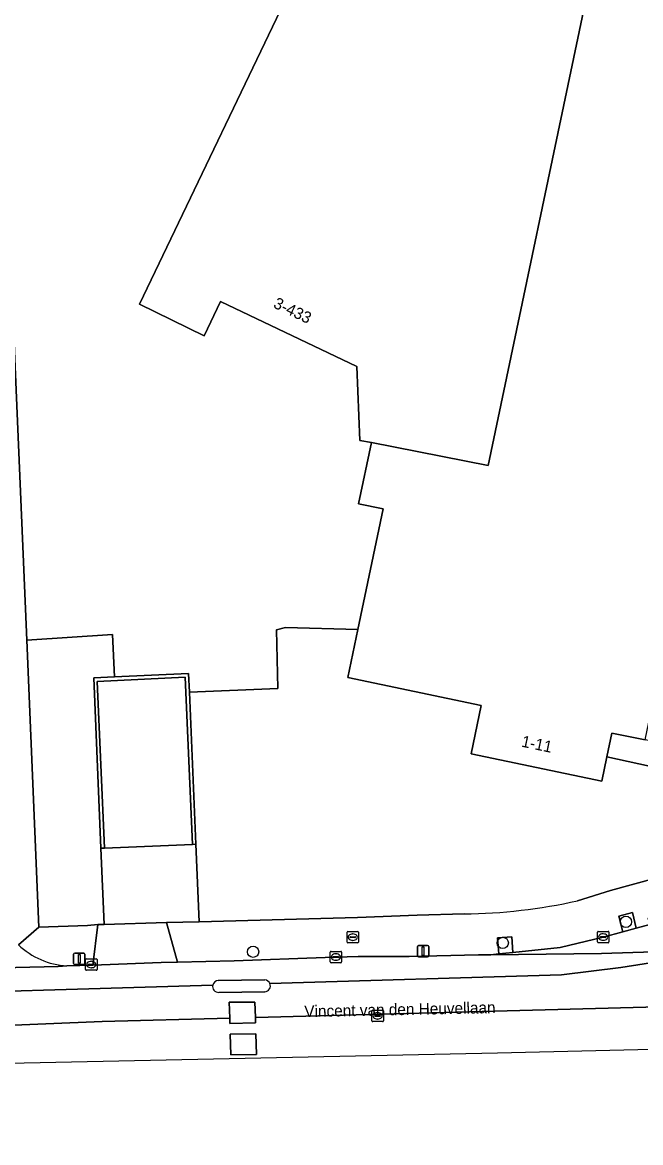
# Model space of a CAD drawing. Extents: x 161241 to 161758, y 384138 to 384885.
# Drawn here: x 161385.2 to 161439, y 384139.3 to 384236.8 of the extents above; entities that cross this region are included whole.
import ezdxf

# ---------------------------------------------------------------- set-up
doc = ezdxf.new("R2010")
doc.units = 0
for name, color, linetype in [('IMGEO_Boom', 7, 'Continuous'), ('IMGEO_Brandkraan', 7, 'Continuous'), ('IMGEO_Erf', 7, 'Continuous'), ('IMGEO_Fietspad_gesloten', 7, 'Continuous'), ('IMGEO_Groenvoorziening', 7, 'Continuous'), ('IMGEO_Kolk', 7, 'Continuous'), ('IMGEO_Lichtmast', 7, 'Continuous'), ('IMGEO_Muur', 7, 'Continuous'), ('IMGEO_Openbare_ruimte_label', 7, 'Continuous'), ('IMGEO_Pand', 7, 'Continuous'), ('IMGEO_Pand_nummerreeks', 7, 'Continuous'), ('IMGEO_Rijbaan_lokaal_gesloten', 7, 'Continuous'), ('IMGEO_Rijbaan_lokaal_open', 7, 'Continuous'), ('IMGEO_Rioolput', 7, 'Continuous'), ('IMGEO_Verkeerseiland_open', 7, 'Continuous'), ('IMGEO_Voetpad_open', 7, 'Continuous')]:
    doc.layers.add(name, color=color, linetype=linetype)

msp = doc.modelspace()

# ---------------------------------------------------------------- linework, layer by layer
at = {"layer": 'IMGEO_Boom'}
for centre in [(161437.743, 384158.555), (161427.028, 384156.723), (161405.286, 384155.947)]:
    msp.add_circle(centre, 0.489, dxfattribs=at)
at = {"layer": 'IMGEO_Brandkraan'}
for p, q in [((161413.464, 384156.795), (161413.464, 384157.647)), ((161413.539, 384157.721), (161414.391, 384157.721)), ((161413.723, 384157.215), (161413.723, 384157.227)), ((161414.161, 384157.178), (161413.763, 384157.178)), ((161413.766, 384157.264), (161414.164, 384157.264)), ((161413.952, 384157.501), (161413.977, 384157.501)), ((161414.207, 384157.227), (161414.207, 384157.215)), ((161414.465, 384157.647), (161414.465, 384156.795)), ((161414.391, 384156.721), (161413.539, 384156.721)), ((161413.975, 384156.941), (161413.95, 384156.941))]:
    msp.add_line(p, q, dxfattribs=at)
for points in [[(161413.464, 384156.795), (161413.464, 384157.647)], [(161413.539, 384157.721), (161414.391, 384157.721)], [(161414.465, 384157.647), (161414.465, 384156.795)], [(161414.391, 384156.721), (161413.539, 384156.721)]]:
    msp.add_lwpolyline(points, dxfattribs=at)
for centre, radius, start, end in [((161413.541, 384157.645), 0.0765, 91.55205, 178.44795), ((161413.541, 384157.645), 0.0765, 91.55205, 178.44795), ((161413.763, 384157.224), 0.0403, 85.87752, 175.75265), ((161413.76, 384157.214), 0.0366, 178.93798, 274.71019), ((161414.164, 384157.221), 0.043, 264.86636, 352.45326), ((161414.168, 384157.226), 0.0386, 1.73085, 96.63898), ((161414.389, 384157.645), 0.0765, 1.55205, 88.44795), ((161414.389, 384157.645), 0.0765, 1.55205, 88.44795), ((161413.541, 384156.797), 0.0765, 181.55205, 268.44795), ((161413.541, 384156.797), 0.0765, 181.55205, 268.44795), ((161414.389, 384156.797), 0.0765, 271.55205, 358.44795), ((161414.389, 384156.797), 0.0765, 271.55205, 358.44795)]:
    msp.add_arc(centre, radius, start, end, dxfattribs=at)
for centre, major_axis, ratio, start_param, end_param in [((161413.951, 384157.221), (-0.387, 0.002), 0.722429, 4.712389, 7.853982), ((161413.976, 384157.221), (-0.39, 0.002), 0.717154, 1.570796, 4.712389)]:
    msp.add_ellipse(centre, major_axis=major_axis, ratio=ratio, start_param=start_param, end_param=end_param, dxfattribs=at)
at = {"layer": 'IMGEO_Erf'}
for points in [[(161403.222, 384286.46), (161382.629, 384295.041), (161382.268, 384292.057), (161381.629, 384276.193), (161381.889, 384271.203), (161384.168, 384216.383), (161385.58, 384183.057), (161393.06, 384183.551), (161393.229, 384179.87), (161399.67, 384180.152), (161399.739, 384178.529), (161407.43, 384178.871), (161407.337, 384183.973), (161408.1, 384184.171), (161414.411, 384183.984), (161416.602, 384194.481), (161414.471, 384194.926), (161415.583, 384200.253), (161414.588, 384200.438), (161414.333, 384206.87)], [(161414.333, 384206.87), (161402.446, 384212.54), (161401.021, 384209.552), (161395.402, 384212.301), (161409.705, 384242.134), (161410.074, 384241.957), (161409.897, 384241.587), (161413.262, 384241.218), (161413.151, 384243.377), (161412.471, 384256.608), (161412.447, 384256.607), (161412.427, 384256.606), (161412.309, 384258.896), (161412.087, 384258.958), (161410.446, 384259.418), (161410.259, 384263.218), (161410.244, 384263.523), (161410.022, 384263.577), (161410.017, 384263.687), (161409.789, 384268.472), (161410.452, 384282.119), (161403.688, 384284.431), (161403.646, 384285.881)]]:
    msp.add_lwpolyline(points, dxfattribs=at)
at = {"layer": 'IMGEO_Fietspad_gesloten'}
msp.add_lwpolyline([(161458.084, 384163.277), (161449.764, 384161.023), (161448.578, 384160.702), (161444.788, 384159.674), (161439.834, 384158.33), (161438.642, 384158.007), (161437.465, 384157.687), (161435.768, 384157.227), (161432.032, 384156.309), (161427.896, 384155.889), (161426.672, 384155.766), (161425.997, 384155.697), (161435.621, 384155.795), (161447.477, 384156.186)], dxfattribs=at)
at = {"layer": 'IMGEO_Groenvoorziening'}
for points in [[(161391.41, 384179.791), (161393.229, 384179.87), (161393.06, 384183.551), (161385.58, 384183.057), (161386.637, 384158.099), (161390.867, 384158.244), (161391.76, 384158.321), (161392.317, 384158.336), (161392.037, 384164.964)], [(161438.312, 384159.38), (161437.14, 384159.04), (161437.465, 384157.687), (161438.642, 384158.007)], [(161427.801, 384157.237), (161426.576, 384157.152), (161426.672, 384155.766), (161427.896, 384155.889)]]:
    msp.add_lwpolyline(points, close=True, dxfattribs=at)
for points in [[(161424.271, 384173.178), (161425.148, 384177.381), (161413.538, 384179.804), (161414.411, 384183.984), (161408.1, 384184.171), (161407.337, 384183.973), (161407.43, 384178.871), (161399.739, 384178.529), (161400.302, 384165.307), (161400.589, 384158.56), (161414.377, 384158.936), (161419.572, 384159.122), (161423.657, 384159.253)], [(161433.522, 384160.391), (161436.394, 384161.282), (161440.318, 384162.357), (161441.305, 384166.747), (161442.601, 384171.491), (161436.086, 384172.902), (161435.648, 384170.803), (161424.271, 384173.178)]]:
    msp.add_lwpolyline(points, dxfattribs=at)
msp.add_arc((161423.309, 384205.596), 46.344, 270.43003, 282.73077, dxfattribs=at)
at = {"layer": 'IMGEO_Kolk'}
for p, q in [((161435.267, 384156.801), (161435.267, 384157.653)), ((161435.342, 384157.727), (161436.194, 384157.727)), ((161435.526, 384157.221), (161435.526, 384157.233)), ((161435.964, 384157.184), (161435.566, 384157.184)), ((161435.569, 384157.27), (161435.967, 384157.27)), ((161435.755, 384157.507), (161435.78, 384157.507)), ((161436.01, 384157.233), (161436.01, 384157.221)), ((161436.268, 384157.653), (161436.268, 384156.801)), ((161436.194, 384156.727), (161435.342, 384156.727)), ((161435.778, 384156.947), (161435.753, 384156.947)), ((161390.702, 384154.413), (161390.702, 384155.265)), ((161390.777, 384155.339), (161391.629, 384155.339)), ((161391.19, 384155.119), (161391.215, 384155.119)), ((161391.703, 384155.265), (161391.703, 384154.413)), ((161411.997, 384155.062), (161411.997, 384155.914)), ((161412.072, 384155.988), (161412.924, 384155.988)), ((161412.256, 384155.482), (161412.256, 384155.494)), ((161412.694, 384155.445), (161412.296, 384155.445)), ((161412.299, 384155.531), (161412.697, 384155.531)), ((161412.508, 384155.208), (161412.483, 384155.208)), ((161412.485, 384155.768), (161412.51, 384155.768)), ((161412.74, 384155.494), (161412.74, 384155.482)), ((161412.998, 384155.914), (161412.998, 384155.062)), ((161391.629, 384154.339), (161390.777, 384154.339)), ((161390.961, 384154.833), (161390.961, 384154.845)), ((161391.399, 384154.796), (161391.001, 384154.796)), ((161391.004, 384154.882), (161391.402, 384154.882)), ((161391.213, 384154.559), (161391.188, 384154.559)), ((161391.445, 384154.845), (161391.445, 384154.833)), ((161412.924, 384154.988), (161412.072, 384154.988))]:
    msp.add_line(p, q, dxfattribs=at)
for points in [[(161435.267, 384156.801), (161435.267, 384157.653)], [(161435.342, 384157.727), (161436.194, 384157.727)], [(161436.268, 384157.653), (161436.268, 384156.801)], [(161436.194, 384156.727), (161435.342, 384156.727)], [(161390.702, 384154.413), (161390.702, 384155.265)], [(161390.777, 384155.339), (161391.629, 384155.339)], [(161391.703, 384155.265), (161391.703, 384154.413)], [(161411.997, 384155.062), (161411.997, 384155.914)], [(161412.072, 384155.988), (161412.924, 384155.988)], [(161412.998, 384155.914), (161412.998, 384155.062)], [(161391.629, 384154.339), (161390.777, 384154.339)], [(161412.924, 384154.988), (161412.072, 384154.988)]]:
    msp.add_lwpolyline(points, dxfattribs=at)
for centre, radius, start, end in [((161435.344, 384157.651), 0.0765, 91.55205, 178.44795), ((161435.344, 384157.651), 0.0765, 91.55205, 178.44795), ((161435.566, 384157.23), 0.0403, 85.87752, 175.75265), ((161435.563, 384157.22), 0.0366, 178.93798, 274.71019), ((161435.967, 384157.227), 0.043, 264.86636, 352.45326), ((161435.971, 384157.232), 0.0386, 1.73085, 96.63898), ((161436.192, 384157.651), 0.0765, 1.55205, 88.44795), ((161436.192, 384157.651), 0.0765, 1.55205, 88.44795), ((161435.344, 384156.803), 0.0765, 181.55205, 268.44795), ((161435.344, 384156.803), 0.0765, 181.55205, 268.44795), ((161436.192, 384156.803), 0.0765, 271.55205, 358.44795), ((161436.192, 384156.803), 0.0765, 271.55205, 358.44795), ((161390.779, 384155.263), 0.0765, 91.55205, 178.44795), ((161390.779, 384155.263), 0.0765, 91.55205, 178.44795), ((161391.627, 384155.263), 0.0765, 1.55205, 88.44795), ((161391.627, 384155.263), 0.0765, 1.55205, 88.44795), ((161412.074, 384155.912), 0.0765, 91.55205, 178.44795), ((161412.074, 384155.912), 0.0765, 91.55205, 178.44795), ((161412.074, 384155.064), 0.0765, 181.55205, 268.44795), ((161412.074, 384155.064), 0.0765, 181.55205, 268.44795), ((161412.296, 384155.491), 0.0403, 85.87752, 175.75265), ((161412.293, 384155.481), 0.0366, 178.93798, 274.71019), ((161412.697, 384155.488), 0.043, 264.86636, 352.45326), ((161412.701, 384155.493), 0.0386, 1.73085, 96.63898), ((161412.922, 384155.912), 0.0765, 1.55205, 88.44795), ((161412.922, 384155.912), 0.0765, 1.55205, 88.44795), ((161412.922, 384155.064), 0.0765, 271.55205, 358.44795), ((161412.922, 384155.064), 0.0765, 271.55205, 358.44795), ((161390.779, 384154.415), 0.0765, 181.55205, 268.44795), ((161390.779, 384154.415), 0.0765, 181.55205, 268.44795), ((161391.001, 384154.842), 0.0403, 85.87752, 175.75265), ((161390.998, 384154.832), 0.0366, 178.93798, 274.71019), ((161391.402, 384154.839), 0.043, 264.86636, 352.45326), ((161391.406, 384154.844), 0.0386, 1.73085, 96.63898), ((161391.627, 384154.415), 0.0765, 271.55205, 358.44795), ((161391.627, 384154.415), 0.0765, 271.55205, 358.44795)]:
    msp.add_arc(centre, radius, start, end, dxfattribs=at)
for centre, major_axis, ratio, start_param, end_param in [((161435.754, 384157.227), (-0.387, 0.002), 0.722429, 4.712389, 7.853982), ((161435.779, 384157.227), (-0.39, 0.002), 0.717154, 1.570796, 4.712389), ((161391.189, 384154.839), (-0.387, 0.002), 0.722429, 4.712389, 7.853982), ((161391.214, 384154.839), (-0.39, 0.002), 0.717154, 1.570796, 4.712389), ((161412.484, 384155.488), (-0.387, 0.002), 0.722429, 4.712389, 7.853982), ((161412.509, 384155.488), (-0.39, 0.002), 0.717154, 1.570796, 4.712389)]:
    msp.add_ellipse(centre, major_axis=major_axis, ratio=ratio, start_param=start_param, end_param=end_param, dxfattribs=at)
at = {"layer": 'IMGEO_Lichtmast'}
for p, q in [((161419.591, 384155.601), (161419.591, 384156.401)), ((161419.591, 384156.401), (161419.591, 384155.601)), ((161419.691, 384156.501), (161420.481, 384156.501)), ((161420.481, 384156.501), (161419.691, 384156.501)), ((161420.581, 384156.401), (161420.581, 384155.601)), ((161420.581, 384155.601), (161420.581, 384156.401)), ((161389.654, 384154.933), (161389.654, 384155.733)), ((161389.654, 384155.733), (161389.654, 384154.933)), ((161389.754, 384155.833), (161390.544, 384155.833)), ((161390.544, 384155.833), (161389.754, 384155.833)), ((161390.644, 384155.733), (161390.644, 384154.933)), ((161390.644, 384154.933), (161390.644, 384155.733)), ((161420.481, 384155.501), (161419.691, 384155.501)), ((161419.691, 384155.501), (161420.481, 384155.501)), ((161390.544, 384154.833), (161389.754, 384154.833)), ((161389.754, 384154.833), (161390.544, 384154.833))]:
    msp.add_line(p, q, dxfattribs=at)
for points in [[(161420.011, 384156.376), (161420.161, 384156.376), (161420.161, 384155.626), (161420.011, 384155.626), (161420.011, 384156.376)], [(161390.074, 384155.708), (161390.224, 384155.708), (161390.224, 384154.958), (161390.074, 384154.958), (161390.074, 384155.708)]]:
    msp.add_lwpolyline(points, dxfattribs=at)
for centre, start, end in [((161419.691, 384156.401), 90, 180), ((161419.691, 384156.401), 90, 180), ((161420.481, 384156.401), 0, 90), ((161420.481, 384156.401), 360, 90), ((161389.754, 384155.733), 90, 180), ((161389.754, 384155.733), 90, 180), ((161390.544, 384155.733), 0, 90), ((161390.544, 384155.733), 360, 90), ((161419.691, 384155.601), 180, 270), ((161419.691, 384155.601), 180, 270), ((161420.481, 384155.601), 270, 0), ((161420.481, 384155.601), 270, 0), ((161389.754, 384154.933), 180, 270), ((161389.754, 384154.933), 180, 270), ((161390.544, 384154.933), 270, 0), ((161390.544, 384154.933), 270, 0)]:
    msp.add_arc(centre, 0.1, start, end, dxfattribs=at)
at = {"layer": 'IMGEO_Muur'}
msp.add_lwpolyline([(161399.739, 384178.529), (161399.67, 384180.152), (161393.229, 384179.87), (161391.41, 384179.791), (161392.037, 384164.964), (161392.337, 384164.977), (161391.717, 384179.474), (161399.383, 384179.831), (161400.002, 384165.294), (161400.302, 384165.307)], close=True, dxfattribs=at)
at = {"layer": 'IMGEO_Pand'}
msp.add_lwpolyline([(161413.151, 384243.377), (161413.262, 384241.218), (161409.897, 384241.587), (161410.074, 384241.957), (161409.705, 384242.134), (161395.402, 384212.301), (161401.021, 384209.552), (161402.446, 384212.54), (161414.333, 384206.87), (161414.588, 384200.438), (161415.583, 384200.253), (161425.758, 384198.275), (161434.318, 384239.067)], close=True, dxfattribs=at)
msp.add_lwpolyline([(161434.318, 384239.067), (161425.758, 384198.275), (161415.583, 384200.253), (161414.471, 384194.926), (161416.602, 384194.481), (161414.411, 384183.984), (161413.538, 384179.804), (161425.148, 384177.381), (161424.271, 384173.178), (161435.648, 384170.803), (161436.086, 384172.902), (161436.521, 384174.985), (161439.412, 384174.382), (161443.732, 384195.077), (161444.116, 384194.997), (161444.215, 384195.469), (161443.954, 384195.524), (161450.857, 384228.917), (161450.895, 384229.101), (161452.162, 384235.232), (161453.42, 384241.315)], dxfattribs=at)
at = {"layer": 'IMGEO_Rijbaan_lokaal_gesloten'}
for points in [[(161392.337, 384164.977), (161400.002, 384165.294), (161399.383, 384179.831), (161391.717, 384179.474)], [(161453.468, 384147.793), (161453.737, 384151.519), (161405.491, 384150.24), (161405.509, 384149.782), (161403.269, 384149.72), (161403.252, 384150.18), (161392.155, 384149.886), (161376.721, 384149.233), (161369.626, 384148.76), (161361.232, 384148.2), (161341.125, 384146.731), (161314.989, 384144.831), (161288.79, 384142.926), (161262, 384140.882), (161261.88, 384139.347), (161350.999, 384145.561), (161426.579, 384147.153)], [(161403.279, 384148.788), (161405.534, 384148.816), (161405.591, 384147.013), (161403.355, 384146.98)]]:
    msp.add_lwpolyline(points, close=True, dxfattribs=at)
for points in [[(161437.318, 384154.582), (161447.477, 384156.186), (161435.621, 384155.795), (161425.997, 384155.697), (161424.925, 384155.676), (161418.887, 384155.534), (161414.448, 384155.534), (161411.559, 384155.465), (161403.634, 384155.167), (161398.71, 384155.049), (161397.291, 384155.015), (161392.098, 384154.814), (161391.334, 384154.79), (161389.077, 384154.72), (161388.306, 384154.657), (161371.088, 384154.255)], [(161403.202, 384151.552), (161405.439, 384151.575), (161405.491, 384150.24), (161453.737, 384151.519), (161454.085, 384156.354), (161447.477, 384156.186), (161437.318, 384154.582), (161432.134, 384153.933), (161406.755, 384153.182)], [(161406.755, 384153.182), (161432.134, 384153.933), (161437.318, 384154.582)], [(161402.26, 384153.444), (161406.312, 384153.498)], [(161334.833, 384149.765), (161370.321, 384152.118), (161401.777, 384153.037)], [(161401.777, 384153.037), (161370.321, 384152.118)], [(161406.304, 384152.476), (161402.294, 384152.419)], [(161376.721, 384149.233), (161392.155, 384149.886), (161403.252, 384150.18), (161403.202, 384151.552)]]:
    msp.add_lwpolyline(points, dxfattribs=at)
for centre, radius, start, end in [((161402.277, 384152.933), 0.511, 91.94396, 168.29437), ((161406.281, 384152.987), 0.512, 272.52131, 22.33698), ((161406.283, 384152.988), 0.511, 22.30129, 86.69679), ((161402.277, 384152.93), 0.512, 167.96336, 271.86629)]:
    msp.add_arc(centre, radius, start, end, dxfattribs=at)
at = {"layer": 'IMGEO_Rijbaan_lokaal_open'}
for points in [[(161448.035, 384197.539), (161443.202, 384173.582), (161439.412, 384174.382), (161436.521, 384174.985), (161436.086, 384172.902), (161442.601, 384171.491), (161441.305, 384166.747), (161440.318, 384162.357), (161444.823, 384163.456), (161445.81, 384167.846), (161447.397, 384174.537), (161450.553, 384190.18), (161454.769, 384194.574), (161458.012, 384197.955), (161464.156, 384229.33), (161465.863, 384238.046), (161462.953, 384238.76), (161465.264, 384250), (161469.159, 384268.947), (161457.031, 384271.325)], [(161371.088, 384154.255), (161388.306, 384154.657), (161389.077, 384154.72)]]:
    msp.add_lwpolyline(points, dxfattribs=at)
for points in [[(161400.302, 384165.307), (161400.002, 384165.294), (161392.337, 384164.977), (161392.037, 384164.964), (161392.317, 384158.336), (161397.762, 384158.484), (161400.589, 384158.56)], [(161405.491, 384150.24), (161405.439, 384151.575), (161403.202, 384151.552), (161403.252, 384150.18), (161403.269, 384149.72), (161405.509, 384149.782)], [(161403.355, 384146.98), (161405.591, 384147.013), (161405.534, 384148.816), (161403.279, 384148.788)]]:
    msp.add_lwpolyline(points, close=True, dxfattribs=at)
msp.add_arc((161389.469, 384161.364), 6.655, 226.17773, 266.62056, dxfattribs=at)
at = {"layer": 'IMGEO_Rioolput'}
for p, q in [((161415.627, 384149.948), (161415.627, 384150.8)), ((161415.702, 384150.874), (161416.554, 384150.874)), ((161415.886, 384150.368), (161415.886, 384150.38)), ((161416.324, 384150.331), (161415.926, 384150.331)), ((161415.929, 384150.417), (161416.327, 384150.417)), ((161416.115, 384150.654), (161416.14, 384150.654)), ((161416.37, 384150.38), (161416.37, 384150.368)), ((161416.628, 384150.8), (161416.628, 384149.948)), ((161416.554, 384149.874), (161415.702, 384149.874)), ((161416.138, 384150.094), (161416.113, 384150.094))]:
    msp.add_line(p, q, dxfattribs=at)
for points in [[(161415.627, 384149.948), (161415.627, 384150.8)], [(161415.702, 384150.874), (161416.554, 384150.874)], [(161416.628, 384150.8), (161416.628, 384149.948)], [(161416.554, 384149.874), (161415.702, 384149.874)]]:
    msp.add_lwpolyline(points, dxfattribs=at)
for centre, radius, start, end in [((161415.704, 384150.798), 0.0765, 91.55205, 178.44795), ((161415.704, 384150.798), 0.0765, 91.55205, 178.44795), ((161415.926, 384150.377), 0.0403, 85.87752, 175.75265), ((161415.923, 384150.367), 0.0366, 178.93798, 274.71019), ((161416.327, 384150.374), 0.043, 264.86636, 352.45326), ((161416.331, 384150.379), 0.0386, 1.73085, 96.63898), ((161416.552, 384150.798), 0.0765, 1.55205, 88.44795), ((161416.552, 384150.798), 0.0765, 1.55205, 88.44795), ((161415.704, 384149.95), 0.0765, 181.55205, 268.44795), ((161415.704, 384149.95), 0.0765, 181.55205, 268.44795), ((161416.552, 384149.95), 0.0765, 271.55205, 358.44795), ((161416.552, 384149.95), 0.0765, 271.55205, 358.44795)]:
    msp.add_arc(centre, radius, start, end, dxfattribs=at)
for centre, major_axis, ratio, start_param, end_param in [((161416.114, 384150.374), (-0.387, 0.002), 0.722429, 4.712389, 7.853982), ((161416.139, 384150.374), (-0.39, 0.002), 0.717154, 1.570796, 4.712389)]:
    msp.add_ellipse(centre, major_axis=major_axis, ratio=ratio, start_param=start_param, end_param=end_param, dxfattribs=at)
at = {"layer": 'IMGEO_Verkeerseiland_open'}
for points in [[(161406.312, 384153.498), (161402.26, 384153.444)], [(161402.294, 384152.419), (161406.304, 384152.476)]]:
    msp.add_lwpolyline(points, dxfattribs=at)
for centre, radius, start, end in [((161402.277, 384152.933), 0.511, 91.94396, 168.29437), ((161406.281, 384152.987), 0.512, 272.52131, 22.33698), ((161406.283, 384152.988), 0.511, 22.30129, 86.69679), ((161402.277, 384152.93), 0.512, 167.96336, 271.86629)]:
    msp.add_arc(centre, radius, start, end, dxfattribs=at)
at = {"layer": 'IMGEO_Voetpad_open'}
for points in [[(161384.861, 384156.562), (161386.637, 384158.099), (161385.58, 384183.057), (161384.168, 384216.383), (161381.889, 384271.203)], [(161437.14, 384159.04), (161438.312, 384159.38), (161438.642, 384158.007), (161439.834, 384158.33), (161439.685, 384158.886), (161444.643, 384160.214), (161444.788, 384159.674), (161448.578, 384160.702), (161448.223, 384162.035), (161449.411, 384162.348), (161449.764, 384161.023), (161458.084, 384163.277), (161458.949, 384168.46), (161457.892, 384166.781), (161456.3, 384166.349), (161447.23, 384164.158), (161446.255, 384163.919), (161444.823, 384163.456), (161440.318, 384162.357), (161436.394, 384161.282), (161433.522, 384160.391)], [(161423.657, 384159.253), (161419.572, 384159.122), (161414.377, 384158.936), (161400.589, 384158.56), (161397.762, 384158.484), (161398.71, 384155.049), (161403.634, 384155.167), (161411.559, 384155.465), (161414.448, 384155.534), (161418.887, 384155.534), (161424.925, 384155.676), (161425.997, 384155.697), (161426.672, 384155.766), (161426.576, 384157.152), (161427.801, 384157.237), (161427.896, 384155.889), (161432.032, 384156.309), (161435.768, 384157.227), (161437.465, 384157.687), (161437.14, 384159.04)], [(161391.76, 384158.321), (161390.867, 384158.244), (161386.637, 384158.099), (161384.861, 384156.562)], [(161389.077, 384154.72), (161391.334, 384154.79), (161391.76, 384158.321)]]:
    msp.add_lwpolyline(points, dxfattribs=at)
msp.add_lwpolyline([(161397.762, 384158.484), (161392.317, 384158.336), (161391.76, 384158.321), (161391.334, 384154.79), (161392.098, 384154.814), (161397.291, 384155.015), (161398.71, 384155.049)], close=True, dxfattribs=at)
for centre, radius, start, end in [((161423.309, 384205.596), 46.344, 270.43003, 282.73077), ((161389.469, 384161.364), 6.655, 226.17773, 266.62056)]:
    msp.add_arc(centre, radius, start, end, dxfattribs=at)

# ---------------------------------------------------------------- texts
at = {"layer": 'IMGEO_Openbare_ruimte_label'}
msp.add_text('Vincent van den Heuvellaan', height=1, rotation=1.20303, dxfattribs=at).set_placement((161409.756, 384150.264))
at = {"layer": 'IMGEO_Pand_nummerreeks'}
for s, rotation, p in [('3-433', 334.49765, (161406.976, 384212.041)), ('1-11', 348.20853, (161428.594, 384173.808))]:
    msp.add_text(s, height=1, rotation=rotation, dxfattribs=at).set_placement(p)

doc.saveas('drawing.dxf')
